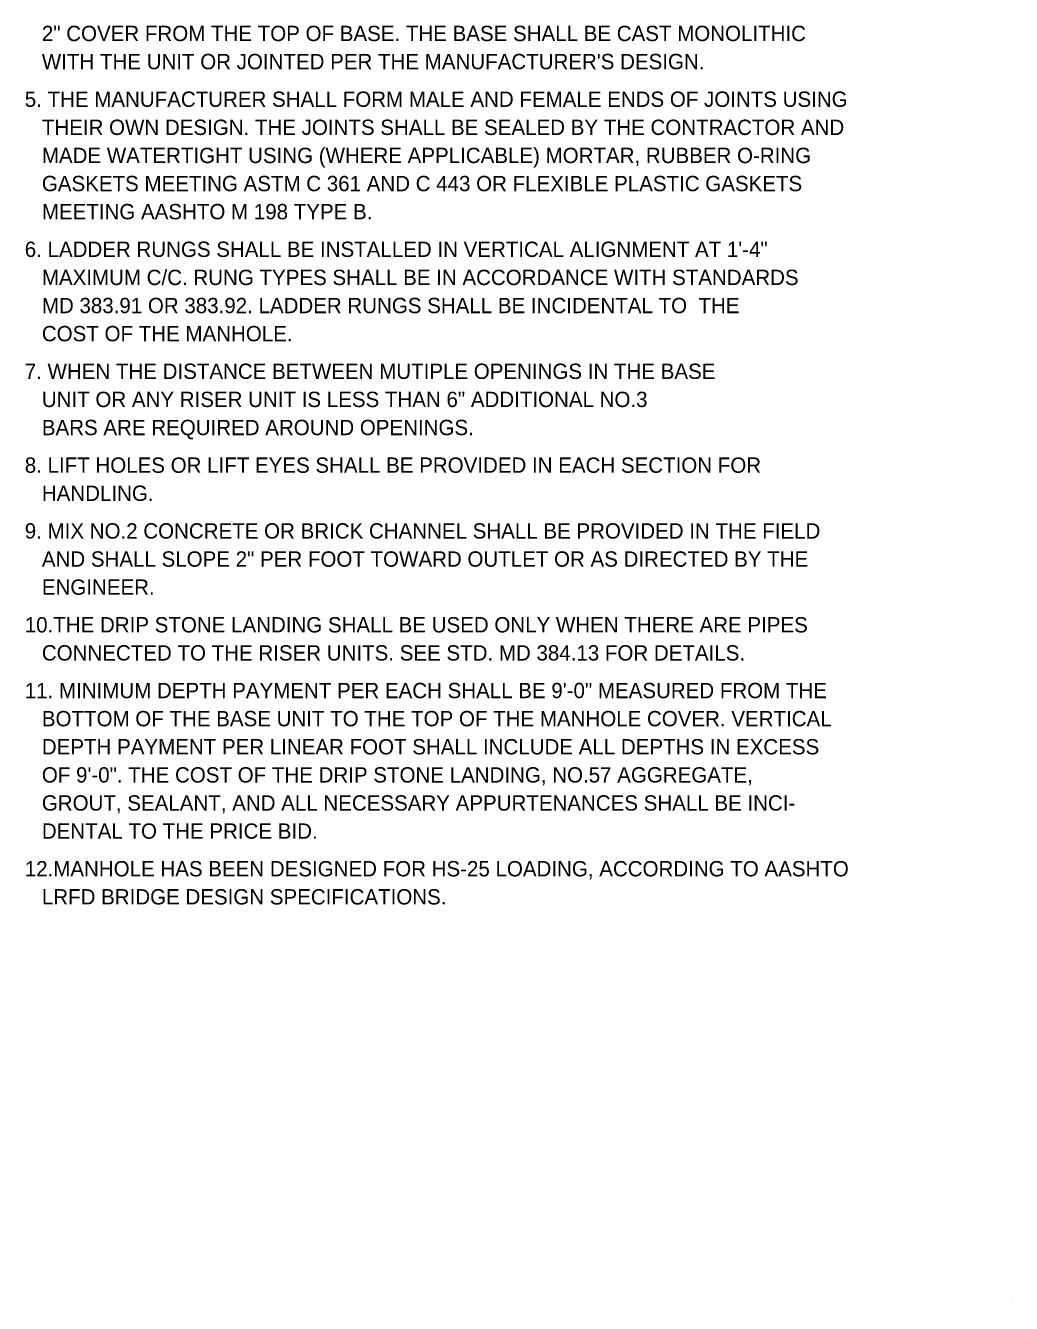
# Model space of a CAD drawing. Extents: x 26.41 to 33.74, y 20.66 to 30.6.
# Drawn here: x 29.883 to 33.738, y 20.656 to 25.656 of the extents above; entities that cross this region are included whole.
import ezdxf

# ---------------------------------------------------------------- set-up
doc = ezdxf.new("R2010")
doc.units = 0
doc.layers.add('DETL-NOTE', color=7, linetype='Continuous')
doc.layers.add('TTLB-TEXT', color=7, linetype='Continuous')

msp = doc.modelspace()

# ---------------------------------------------------------------- linework, layer by layer
at = {"layer": 'TTLB-TEXT'}
msp.add_line((33.7384, 20.6558), (33.7384, 20.6558), dxfattribs=at)

# ---------------------------------------------------------------- texts
at = {"layer": 'DETL-NOTE'}
for s, p in [('   2" COVER FROM THE TOP OF BASE. THE BASE SHALL BE CAST MONOLITHIC ', (29.8803, 25.5948)), ("   WITH THE UNIT OR JOINTED PER THE MANUFACTURER'S DESIGN.", (29.8803, 25.4848)), ('5. THE MANUFACTURER SHALL FORM MALE AND FEMALE ENDS OF JOINTS USING', (29.8803, 25.3375)), ('   THEIR OWN DESIGN. THE JOINTS SHALL BE SEALED BY THE CONTRACTOR AND', (29.8803, 25.2275)), ('   MADE WATERTIGHT USING (WHERE APPLICABLE) MORTAR, RUBBER O-RING', (29.8803, 25.1175)), ('   GASKETS MEETING ASTM C 361 AND C 443 OR FLEXIBLE PLASTIC GASKETS', (29.8803, 25.0075)), ('   MEETING AASHTO M 198 TYPE B.', (29.8803, 24.8976)), ('6. LADDER RUNGS SHALL BE INSTALLED IN VERTICAL ALIGNMENT AT 1\'-4"', (29.8803, 24.7502)), ('   MAXIMUM C/C. RUNG TYPES SHALL BE IN ACCORDANCE WITH STANDARDS', (29.8803, 24.6403)), ('   MD 383.91 OR 383.92. LADDER RUNGS SHALL BE INCIDENTAL TO  THE', (29.8803, 24.5303)), ('   COST OF THE MANHOLE.', (29.8803, 24.4203)), ('7. WHEN THE DISTANCE BETWEEN MUTIPLE OPENINGS IN THE BASE', (29.8803, 24.273)), ('   UNIT OR ANY RISER UNIT IS LESS THAN 6" ADDITIONAL NO.3', (29.8803, 24.163)), ('   BARS ARE REQUIRED AROUND OPENINGS.', (29.8803, 24.053)), ('8. LIFT HOLES OR LIFT EYES SHALL BE PROVIDED IN EACH SECTION FOR', (29.8803, 23.9057)), ('   HANDLING.', (29.8803, 23.7957)), ('9. MIX NO.2 CONCRETE OR BRICK CHANNEL SHALL BE PROVIDED IN THE FIELD', (29.8803, 23.6484)), ('   AND SHALL SLOPE 2" PER FOOT TOWARD OUTLET OR AS DIRECTED BY THE', (29.8803, 23.5384)), ('   ENGINEER.', (29.8803, 23.4285)), ('10.THE DRIP STONE LANDING SHALL BE USED ONLY WHEN THERE ARE PIPES', (29.8803, 23.2811)), ('   CONNECTED TO THE RISER UNITS. SEE STD. MD 384.13 FOR DETAILS.', (29.8803, 23.1712)), ('11. MINIMUM DEPTH PAYMENT PER EACH SHALL BE 9\'-0" MEASURED FROM THE', (29.8803, 23.0239)), ('   BOTTOM OF THE BASE UNIT TO THE TOP OF THE MANHOLE COVER. VERTICAL', (29.8803, 22.9139)), ('   DEPTH PAYMENT PER LINEAR FOOT SHALL INCLUDE ALL DEPTHS IN EXCESS', (29.8803, 22.8039)), ('   OF 9\'-0". THE COST OF THE DRIP STONE LANDING, NO.57 AGGREGATE,', (29.8803, 22.6939)), ('   GROUT, SEALANT, AND ALL NECESSARY APPURTENANCES SHALL BE INCI-', (29.8803, 22.584)), ('   DENTAL TO THE PRICE BID.', (29.8803, 22.474)), ('12.MANHOLE HAS BEEN DESIGNED FOR HS-25 LOADING, ACCORDING TO AASHTO', (29.8803, 22.3267)), ('   LRFD BRIDGE DESIGN SPECIFICATIONS.', (29.8803, 22.2167))]:
    msp.add_text(s, height=0.05998, dxfattribs=at).set_placement(p)

doc.saveas('drawing.dxf')
